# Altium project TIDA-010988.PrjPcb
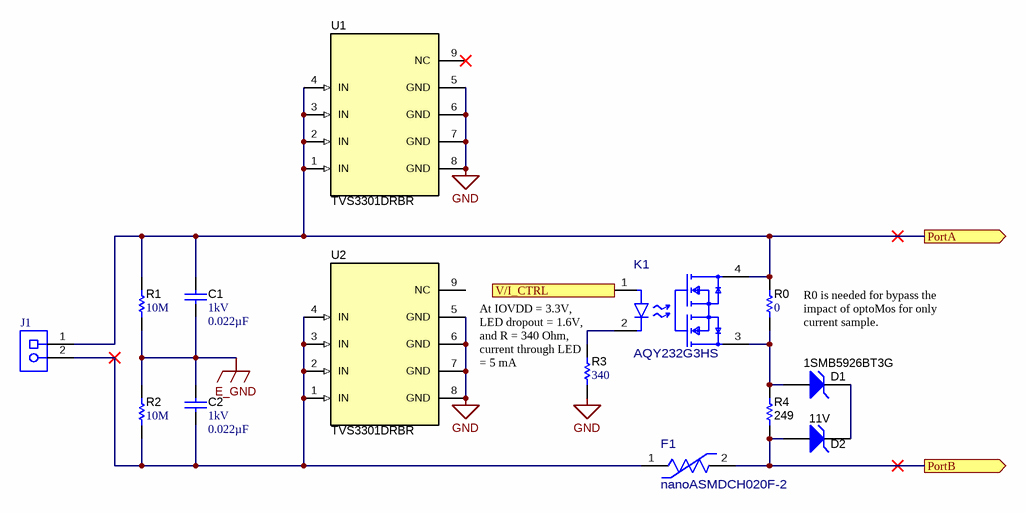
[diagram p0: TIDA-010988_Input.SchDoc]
CopyrightYear: 2025; PCB_Layout: Donna Xu; PCB_Rev: E1; PRJ_Customer: Public Release; PRJ_Engineer: Donna Xu; PRJ_Number: TIDA-010988; PRJ_Title: 8 CH V and I AIN module; SCH_Rev: E1; TechSupport: http://www.ti.com/support; TID: N/A
4 sheets, 173 parts. Net scope: flat (ports and power ports of the same name join across sheets).
Board file: TIDA-010988.PcbDoc
Sheets:
  TIDA-010988_Input.SchDoc
  TIDA-010988_ADC+MCU.SchDoc
  TIDA-010988_Power.SchDoc
  TIDA-010988_Hardware.SchDoc

## Sheet TIDA-010988_Input.SchDoc: INPUT
size A4; Date: Not shown in title block; ApprovedBy: Not shown in title block; CheckedBy: Not shown in title block; Author: Not shown in title block; CompanyName: Not shown in title block; DrawnBy: Donna Xu; Engineer: Not shown in title block; Organization: Not shown in title block; Address1: Not shown in title block; Address2: Not shown in title block; Address3: Not shown in title block; Address4: Not shown in title block; DocumentNumber: 1; Revision: Use project parameter SCH_Rev; SheetNumber: 2; SheetTotal: 5; PageSetup: Record=PageOptions¦CenterHorizontal=True¦CenterVertical=True¦PrintScale=0.93¦XCorrection=1.00¦YCorrection=1.00¦PrintKind=0¦BorderSize=5000000¦LeftOffset=0¦BottomOffset=0¦Orientation=2¦PaperLength=1000¦PaperWidth=1000¦Scale=100¦PaperSource=15¦PrintQuality=600¦MediaType=1¦DitherType=10¦PaperKind=Letter¦PrintScaleMode=1

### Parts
C1  VDC_V: 1kV  ValueDisplayed: 0.022µF  [1206_190]  (hidden comment: C1206C223KDRACTU)
C2  VDC_V: 1kV  ValueDisplayed: 0.022µF  [1206_190]  (hidden comment: C1206C223KDRACTU)
D1  1SMB5926BT3G  value 11V  [SMB]
D2  1SMB5926BT3G  [SMB]  (value not drawn)
F1  nanoASMDCH020F-2  [FP-nanoASMDCH020F-2_1206-MFG]
J1  691210910002  [Wurth_691210910002]  (value not drawn)
K1  AQY232G3HS  [FP-AQY232G3HS_SOP4-MFG]
R0  ValueDisplayed: 0  [0603]  (hidden comment: CRCW06030000Z0EA)
R1  ValueDisplayed: 10M  [0603]  (hidden comment: CRCW060310M0DHEAP)
R2  ValueDisplayed: 10M  [0603]  (hidden comment: CRCW060310M0DHEAP)
R3  ValueDisplayed: 340  [0603]  (hidden comment: RT0603BRD07340RL)
R4  ValueDisplayed: 249  [1206]  (hidden comment: TNPW1206249RBEEA)
U1  TVS3301DRBR  [DRB0008A]
U2  TVS3301DRBR  [DRB0008A]

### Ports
PortA (out), PortB (out), V/I_CTRL (in)

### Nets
E_GND: C1.2 C2.1 R1.1 R2.2
GND: R3.1 U1.5(GND) U1.6(GND) U1.7(GND) U1.8(GND) U2.5(GND) U2.6(GND) U2.7(GND) U2.8(GND)
PortA: C1.1 J1.1 K1.4(2_DRAIN) R0.2 R1.2 U1.1(IN) U1.2(IN) U1.3(IN) U1.4(IN) ; port PortA
PortB: D2.2(A) F1.2 R4.1 ; port PortB
V/I_CTRL: K1.1(ANODE) ; port V/I_CTRL
NetC2_2: C2.2 F1.1 J1.2 R2.1 U2.1(IN) U2.2(IN) U2.3(IN) U2.4(IN)
NetD1_1: D1.1(K) D2.1(K)
NetD1_2: D1.2(A) K1.3(1_DRAIN) R0.1 R4.2
NetK1_2: K1.2(CATHODE) R3.2

Not connected (* = marked no-connect by the designer): U1 9(NC)*; U2 9(NC)

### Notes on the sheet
- R0 is needed for bypass the impact of optoMos for only current sample.
- (near R3) At IOVDD = 3.3V,
  LED dropout = 1.6V,
  and R = 340 Ohm, current through LED = 5 mA

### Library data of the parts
C1 C2 = CMP-0084048-1: CAP, CERM, 0.022 µF, 1000 V,+/- 10%, X7R, AEC-Q200 Grade 1, 1206; Manufacturer: Kemet; TaMin_C: -55°C; Polarized: N; SizeAreaWB_mm2: 10.92; U/M: EA; Value: 0.022uF; TaMax_C: 125°C; SizeZ_mm: 1.9; SizeX_mm: 3.2; SizeY_mm: 1.6; Cap_Case: 1206; Value2: 1000V; SizeArea_mm2: 5.12; AEC Qualified: Y; Cap_F: 22nF; AEC Grade: 1; AEC Category: Q200
D1 = CMP-0005627-4: Diode, Zener, 11 V, 550 mW, SMB; Manufacturer: ON Semiconductor; AEC Category: Q101; SizeArea_mm2: 21.336; Power_W: 550mW; SizeY_mm: 3.81; SizeZ_mm: 2.6; Value1: 0.55W; SizeAreaWB_mm2: 44.156; RJA_CperW: 226; SizeX_mm: 5.6
D2 = CMP-0005627-4: Diode, Zener, 11 V, 550 mW, SMB; Manufacturer: ON Semiconductor; Value: 11V; AEC Category: Q101; SizeArea_mm2: 21.336; Power_W: 550mW; SizeY_mm: 3.81; SizeZ_mm: 2.6; Value1: 0.55W; SizeAreaWB_mm2: 44.156; RJA_CperW: 226; SizeX_mm: 5.6
F1 = CMP-0125283-2: Polymeric PTC Resettable Fuse 30V 200 mA Ih Surface Mount 1206 (3216 Metric), Concave; Manufacturer: Littelfuse; SizeZ_mm: 0.85mm; AEC Grade: Grade 1; AEC Qualified: Yes; Hold Current: 0.2A; Res_ohm: 0.6-4.5Ω; Trip Current: 0.6A; Trip Time: 0.01s
J1 = CMP-0054769-2: Receptacle, 2.54mm, 2x1, Tin, R/A, TH; Manufacturer: Wurth Elektronik; Row_Count: 1; Cert_UL: Y; CT: FALSE; Gender: Female; Pitch_mm: 2.54; Voltage_V: 150V; Current_A: 6A
K1 = CMP-0125248-1: Relay SSR 1mA 1.75V DC-IN 2A 60V AC/DC-OUT 4-Pin SOP Tube; Manufacturer: Panasonic; Contact Form: SPST-NO; SizeZ_mm: 2.4mm; AEC Qualified: No; Cap_F: 0.8pF; Input Current: 20mA; Max Power Dissipation: 530mW; On State Resistance: 0.07Ω; Output Voltage: 48V; Standoff Height: 0.1mm; TaMax_C: +125°C; TaMin_C: -40°C; TJmax_C: +130°C; Voltage_Isolation_Vrms: 3750Vrms
R0 = CMP-0025697-4: RES, 0, 5%, 0.1 W, AEC-Q200 Grade 0, 0603; Manufacturer: Vishay-Dale; Power_W: 100mW; TempCo: 200 ppm/C; Value_Code: 0000; Value: 0; EIA_Code: E24; SizeX_mm: 1.6; SizeY_mm: 0.8; SizeZ_mm: 1; Value2: 0.1W; SizeArea_mm2: 1.28; AEC Qualified: Y; VDC_V: 75V; AEC Category: Q200
R1 R2 = CMP-0023358-4: RES, 10 M, 0.5%, 0.1 W, AEC-Q200 Grade 0, 0603; Manufacturer: Vishay-Dale; Power_W: 100mW; TempCo: 50 ppm/C; Value_Code: 10M0; Value: 10Meg; EIA_Code: E24; SizeX_mm: 1.6; SizeY_mm: 0.8; SizeZ_mm: 1; Value2: 0.1W; SizeArea_mm2: 1.28; AEC Qualified: Y; VDC_V: 75V; AEC Grade: 0; AEC Category: Q200
R3 = CMP-0024131-2: RES, 340, 0.1%, 0.1 W, 0603; Manufacturer: Yageo America; Power_W: 100mW; TempCo: 25 ppm/C; Value_Code: 340R; U/M: EA; Value: 340; EIA_Code: E192; SizeX_mm: 1.6; SizeY_mm: 0.8; SizeZ_mm: 1; Value2: 0.1W; SizeArea_mm2: 1.28; VDC_V: 75V; AEC Category: Q200
R4 = CMP-0018822-2: RES, 249, 0.1%, 0.25 W, 1206; Manufacturer: Vishay-Dale; Power_W: 250mW; TempCo: 25 ppm/C; Value_Code: 249R; U/M: EA; Value: 249; EIA_Code: E192; SizeX_mm: 3.2; SizeY_mm: 1.6; SizeZ_mm: 1.35; Value2: 0.25W; SizeArea_mm2: 5.12; VDC_V: 200V; AEC Category: Q200
U1 U2 = CMP-0081715-3: 33 V Bidirectional Flat-Clamp Surge Protection Device, DRB0008A (VSON-8); Alternate PartNumber: TVS3301DRBT; Alternate Manufacturer: Texas Instruments; SizeZ_mm: 1.0; SizeX_mm: 3.0; AEC Category: Q200; SizeAreaWB_mm2: 16.0; CompType: IC; Rating: Catalog; SizeArea_mm2: 9.0; AEC Qualified: N

## Sheet TIDA-010988_ADC+MCU.SchDoc
size 431 x 279 mm; Date: Not shown in title block; ApprovedBy: Not shown in title block; CheckedBy: Not shown in title block; Author: Not shown in title block; CompanyName: Not shown in title block; DrawnBy: Donna Xu; Engineer: Not shown in title block; Organization: Not shown in title block; Address1: Not shown in title block; Address2: Not shown in title block; Address3: Not shown in title block; Address4: Not shown in title block; DocumentNumber: 2; Revision: Use project parameter SCH_Rev; SheetNumber: 3; SheetTotal: 5; PageSetup: Record=PageOptions¦CenterHorizontal=True¦CenterVertical=True¦PrintScale=1.00¦XCorrection=1.00¦YCorrection=1.00¦PrintKind=0¦BorderSize=5000000¦LeftOffset=0¦BottomOffset=0¦Orientation=2¦PaperLength=1000¦PaperWidth=1000¦Scale=100¦PaperSource=15¦PrintQuality=600¦MediaType=1¦DitherType=10¦PaperKind=Letter¦PrintScaleMode=1
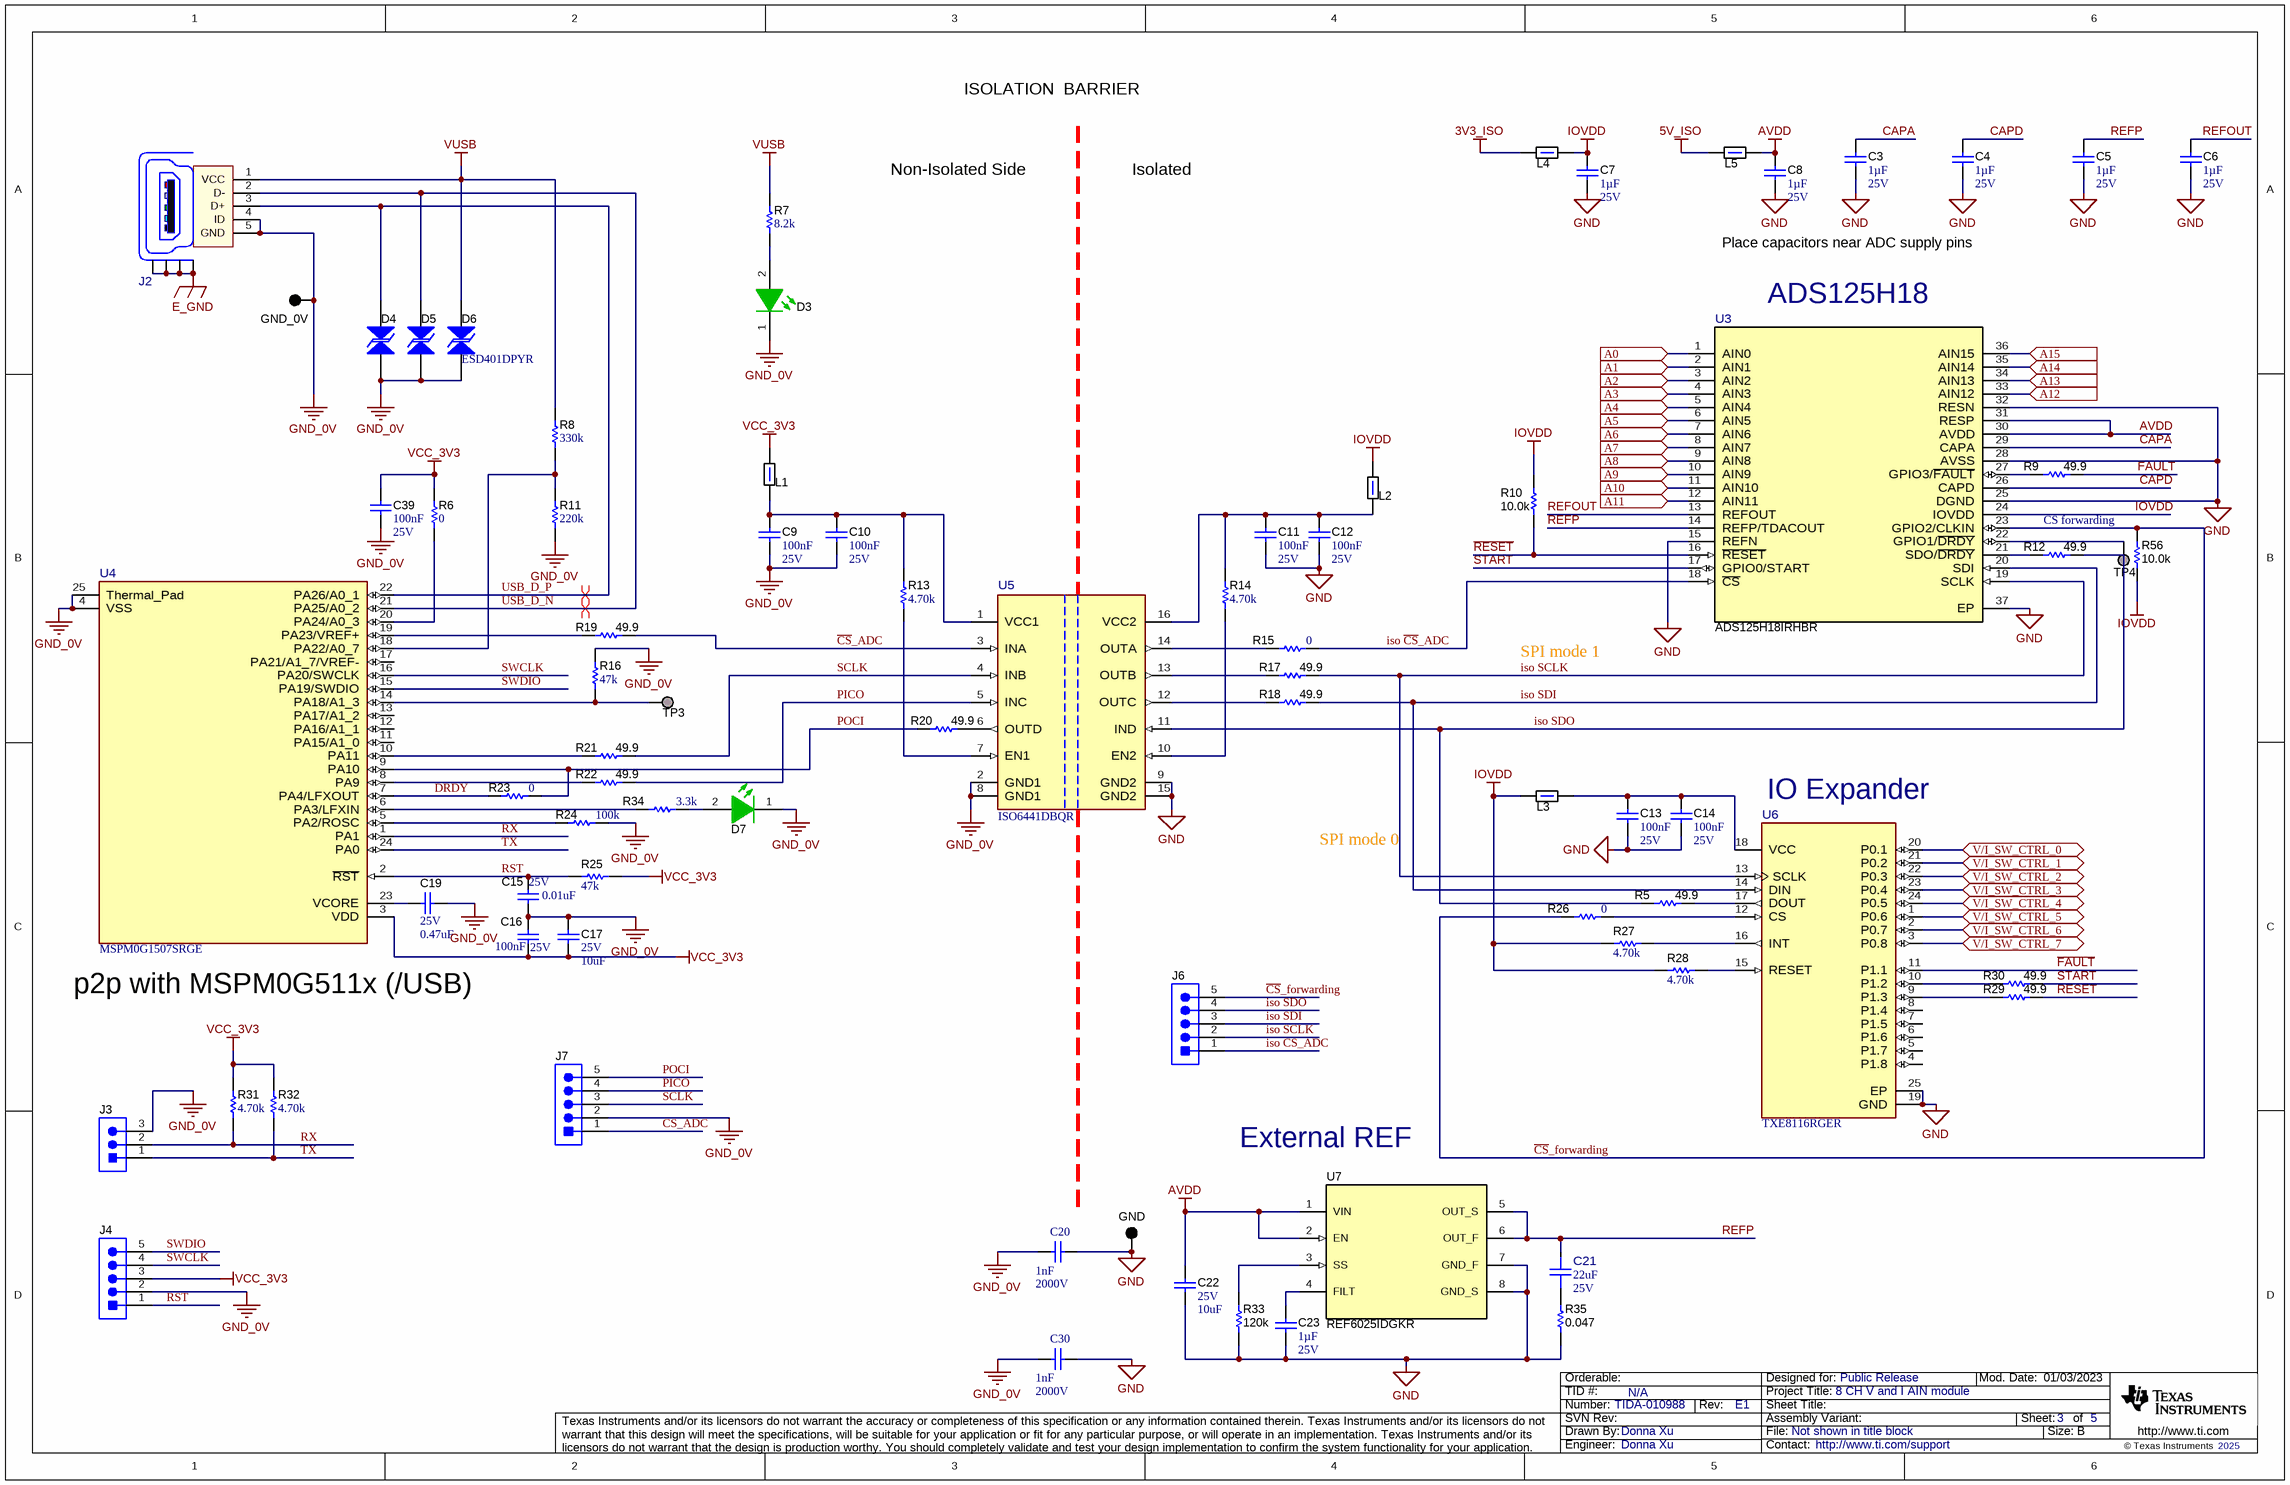
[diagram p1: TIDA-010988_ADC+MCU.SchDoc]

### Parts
C3  Cap_F: 1µF  VDC_V: 25V  [0603]  (hidden comment: 885012206076)
C4  Cap_F: 1µF  VDC_V: 25V  [0603]  (hidden comment: 885012206076)
C5  Cap_F: 1µF  VDC_V: 25V  [0603]  (hidden comment: 885012206076)
C6  Cap_F: 1µF  VDC_V: 25V  [0603S]  (hidden comment: 885012206076)
C7  Cap_F: 1µF  VDC_V: 25V  [0603S]  (hidden comment: 885012206076)
C8  Cap_F: 1µF  VDC_V: 25V  [0603]  (hidden comment: 885012206076)
C9  Cap_F: 100nF  VDC_V: 25V  [0603]  (hidden comment: 885012206071)
C10  Cap_F: 100nF  VDC_V: 25V  [0603]  (hidden comment: 885012206071)
C11  Cap_F: 100nF  VDC_V: 25V  [0603]  (hidden comment: 885012206071)
C12  Cap_F: 100nF  VDC_V: 25V  [0603]  (hidden comment: 885012206071)
C13  Cap_F: 100nF  VDC_V: 25V  [0603]  (hidden comment: 885012206071)
C14  Cap_F: 100nF  VDC_V: 25V  [0603]  (hidden comment: 885012206071)
C15  VDC_V: 25V  ValueDisplayed: 0.01uF  [0603]  (hidden comment: C0603H103J3GACTU)
C16  Cap_F: 100nF  VDC_V: 25V  [0603]  (hidden comment: 885012206071)
C17  VDC_V: 25V  ValueDisplayed: 10uF  [1206]  (hidden comment: 885012208069)
C19  VDC_V: 25V  ValueDisplayed: 0.47uF  [0805_HV]  (hidden comment: 08053D474KAT2A)
C20  Cap_F: 1nF  Rated Voltage (DC): 2000V  [WCAP-CSMH_1206_L3.2W1.6H1.6]  (hidden comment: 885342208024)
C21  ValueDisplayed: 22uF  VDC_V: 25V  [FP-885012209074_1210-MFG]  (hidden comment: 885012209074)
C22  VDC_V: 25V  ValueDisplayed: 10uF  [1206]  (hidden comment: 885012208069)
C23  Cap_F: 1µF  VDC_V: 25V  [0603]  (hidden comment: 885012206076)
C30  Cap_F: 1nF  Rated Voltage (DC): 2000V  [WCAP-CSMH_1206_L3.2W1.6H1.6]  (hidden comment: 885342208024)
C39  Cap_F: 100nF  VDC_V: 25V  [0603]  (hidden comment: 885012206071)
D3  150040GS73240  [WL-SMCC_0402_Green]  (value not drawn)
D4  ESD401DPYR  [DPY0002A]  (value not drawn)
D5  ESD401DPYR  [DPY0002A]  (value not drawn)
D6  ESD401DPYR  [DPY0002A]
D7  150040GS73240  [WL-SMCC_0402_Green]  (value not drawn)
J2  629105150521  [FP-629105150521_CONN_USB_8MM0_6MM6-MFG]  (value not drawn)
J3  61300311121  [WURTH_61300311121]  (value not drawn)
J4  M22-2510505  [Harwin_M22-2510505]  (value not drawn)
J6  M22-2510505  [Harwin_M22-2510505]  (value not drawn)
J7  M22-2510505  [Harwin_M22-2510505]  (value not drawn)
L1  782633601  [0603]  (value not drawn)
L2  782633601  [0603]  (value not drawn)
L3  782633601  [0603]  (value not drawn)
L4  782633601  [0603]  (value not drawn)
L5  782633601  [0603]  (value not drawn)
R5  ValueDisplayed: 49.9  [0603]  (hidden comment: RT0603DRE0749R9L)
R6  ValueDisplayed: 0  [0603]  (hidden comment: CRCW06030000Z0EA)
R7  ValueDisplayed: 8.2k  [0603]  (hidden comment: CRCW06038K20JNEA)
R8  ValueDisplayed: 330k  [0603]  (hidden comment: RC0603FR-07330KL)
R9  ValueDisplayed: 49.9  [0603]  (hidden comment: RT0603DRE0749R9L)
R10  ValueDisplayed: 10.0k  [0603S]  (hidden comment: CRCW060310K0FKEA)
R11  ValueDisplayed: 220k  [0603]  (hidden comment: RC0603FR-07220KL)
R12  ValueDisplayed: 49.9  [0603S]  (hidden comment: RT0603DRE0749R9L)
R13  ValueDisplayed: 4.70k  [0603S]  (hidden comment: RC0603FR-074K7L)
R14  ValueDisplayed: 4.70k  [0603S]  (hidden comment: RC0603FR-074K7L)
R15  ValueDisplayed: 0  [0603S]  (hidden comment: CRCW06030000Z0EA)
R16  ValueDisplayed: 47k  [0603]  (hidden comment: RC0603JR-0747KL)
R17  ValueDisplayed: 49.9  [0603S]  (hidden comment: RT0603DRE0749R9L)
R18  ValueDisplayed: 49.9  [0603S]  (hidden comment: RT0603DRE0749R9L)
R19  ValueDisplayed: 49.9  [0603]  (hidden comment: RT0603DRE0749R9L)
R20  ValueDisplayed: 49.9  [0603S]  (hidden comment: RT0603DRE0749R9L)
R21  ValueDisplayed: 49.9  [0603S]  (hidden comment: RT0603DRE0749R9L)
R22  ValueDisplayed: 49.9  [0603S]  (hidden comment: RT0603DRE0749R9L)
R23  ValueDisplayed: 0  [0603S]  (hidden comment: CRCW06030000Z0EA)
R24  ValueDisplayed: 100k  [0603]  (hidden comment: ERA-3AEB104V)
R25  ValueDisplayed: 47k  [0603]  (hidden comment: RC0603JR-0747KL)
R26  ValueDisplayed: 0  [0603]  (hidden comment: CRCW06030000Z0EA)
R27  ValueDisplayed: 4.70k  [0603]  (hidden comment: RC0603FR-074K7L)
R28  ValueDisplayed: 4.70k  [0603]  (hidden comment: RC0603FR-074K7L)
R29  ValueDisplayed: 49.9  [0603]  (hidden comment: RT0603DRE0749R9L)
R30  ValueDisplayed: 49.9  [0603]  (hidden comment: RT0603DRE0749R9L)
R31  ValueDisplayed: 4.70k  [0603]  (hidden comment: RC0603FR-074K7L)
R32  ValueDisplayed: 4.70k  [0603]  (hidden comment: RC0603FR-074K7L)
R33  ValueDisplayed: 120k  [0603]  (hidden comment: RG1608P-124-B-T5)
R34  ValueDisplayed: 3.3k  [0402]  (hidden comment: CRCW04023K30JNED)
R35  ValueDisplayed: 0.047  [0603]  (hidden comment: ERJ-L03KF47MV)
R56  ValueDisplayed: 10.0k  [0603S]  (hidden comment: CRCW060310K0FKEA)
TP1  GND  [Keystone5001]
TP2  GND_0V  [Keystone5001]
TP3  PA18  [TP_SM_1MM]  (value not drawn)  (no BOM)
TP4  DRDY  [TP_SM_1MM]  (value not drawn)  (no BOM)
U3  ADS125H18IRHBR  [RHB0036A-MFG]
U4  MSPM0G1507SRGE  [RGE0024H-MFG]
U5  ISO6441DBQR  [DBQ0016A-MFG]
U6  TXE8116RGER  [RGE0024F-MFG]
U7  REF6025IDGKR  [DGK0008A_N]

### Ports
A0 (in), A1 (in), A2 (in), A3 (in), A4 (in), A5 (in), A6 (in), A7 (in), A8 (in), A9 (in), A10 (in), A11 (in), A12 (in), A13 (in), A14 (in), A15 (in), V/I_SW_CTRL_0 (bidir), V/I_SW_CTRL_1 (bidir), V/I_SW_CTRL_2 (bidir), V/I_SW_CTRL_3 (bidir), V/I_SW_CTRL_4 (bidir), V/I_SW_CTRL_5 (bidir), V/I_SW_CTRL_6 (bidir), V/I_SW_CTRL_7 (bidir)

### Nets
3V3_ISO: L4.2
5V_ISO: L5.2
AVDD: C8.1 C22.1 L5.1 U3.30(AVDD) U3.31(RESP) U7.1(VIN) U7.2(EN)
E_GND: J2.Z1(Shield) J2.Z2(Shield) J2.Z3(Shield) J2.Z4(Shield)
GND: C3.2 C4.2 C5.2 C6.2 C7.2 C8.2 C11.2 C12.2 C13.2 C14.2 C20.2 C22.2 C23.2 C30.2 R33.1 R35.1 TP1.1 U3.15(REFN) U3.25(DGND) U3.28(AVSS) U3.32(RESN) U3.37(EP) U5.9(GND2) U5.15(GND2) U6.19(GND) U6.25(EP) U7.7(GND_F) U7.8(GND_S)
GND_0V: C9.2 C10.2 C15.2 C16.1 C17.1 C19.1 C20.1 C30.1 C39.2 D3.1(K) D4.1 D5.1 D6.1 D7.1(K) J2.4(ID) J2.5(GND) J3.3 J4.2 J7.2 R11.1 R16.1 R24.2 TP2.1 U4.4(VSS) U4.25(Thermal_Pad) U5.2(GND1) U5.8(GND1)
IOVDD: C7.1 L2.2 L3.1 L4.1 R10.1 R27.2 R28.2 R56.1 U3.24(IOVDD)
VCC_3V3: C16.2 C17.2 C39.1 J4.3 L1.1 R6.2 R25.1 R31.2 R32.2 U4.3(VDD)
VUSB: D6.2 J2.1(VCC) R7.2 R8.2
A0: U3.1(AIN0) ; port A0
A1: U3.2(AIN1) ; port A1
A2: U3.3(AIN2) ; port A2
A3: U3.4(AIN3) ; port A3
A4: U3.5(AIN4) ; port A4
A5: U3.6(AIN5) ; port A5
A6: U3.7(AIN6) ; port A6
A7: U3.8(AIN7) ; port A7
A8: U3.9(AIN8) ; port A8
A9: U3.10(AIN9) ; port A9
A10: U3.11(AIN10) ; port A10
A11: U3.12(AIN11) ; port A11
A12: U3.33(AIN12) ; port A12
A13: U3.34(AIN13) ; port A13
A14: U3.35(AIN14) ; port A14
A15: U3.36(AIN15) ; port A15
~{CS}_ADC: J7.1 R19.2 U5.3(INA)
~{CS}_forwarding: J6.5 R26.1 R56.2 U3.23(GPIO2/CLKIN)
CAPA: C3.1 U3.29(CAPA)
CAPD: C4.1 U3.26(CAPD)
DRDY: R23.1 U4.7(PA4/LFXOUT)
~{FAULT}: R9.2 U6.11(P1.1)
iso ~{CS}_ADC: J6.1 R15.2 U3.18(~{CS})
iso SCLK: J6.2 R17.2 U3.19(SCLK) U6.13(SCLK)
iso SDI: J6.3 R18.2 U3.20(SDI) U6.14(DIN)
iso SDO: J6.4 R5.1 R12.2 U5.11(IND)
PICO: J7.4 R22.2 U5.5(INC)
POCI: J7.5 R20.1 R23.2 U4.9(PA10)
~{RESET}: R10.2 R29.2 U3.16(~{RESET})
REFOUT: C6.1 U3.13(REFOUT)
REFP: C5.1 C21.2 U3.14(REFP/TDACOUT) U7.5(OUT_S) U7.6(OUT_F)
RST: C15.1 J4.1 R25.2 U4.2(~{RST})
RX: J3.2 R31.1 U4.1(PA1)
SCLK: J7.3 R21.2 U5.4(INB)
START: R30.2 U3.17(GPIO0/START)
SWCLK: J4.4 U4.16(PA20/SWCLK)
SWDIO: J4.5 U4.15(PA19/SWDIO)
TX: J3.1 R32.1 U4.24(PA0)
USB_D_N: D5.2 J2.2(D-) U4.21(PA25/A0_2)
USB_D_P: D4.2 J2.3(D+) U4.22(PA26/A0_1)
V/I_SW_CTRL_0: U6.20(P0.1) ; port V/I_SW_CTRL_0
V/I_SW_CTRL_1: U6.21(P0.2) ; port V/I_SW_CTRL_1
V/I_SW_CTRL_2: U6.22(P0.3) ; port V/I_SW_CTRL_2
V/I_SW_CTRL_3: U6.23(P0.4) ; port V/I_SW_CTRL_3
V/I_SW_CTRL_4: U6.24(P0.5) ; port V/I_SW_CTRL_4
V/I_SW_CTRL_5: U6.1(P0.6) ; port V/I_SW_CTRL_5
V/I_SW_CTRL_6: U6.2(P0.7) ; port V/I_SW_CTRL_6
V/I_SW_CTRL_7: U6.3(P0.8) ; port V/I_SW_CTRL_7
NetC9_1: C9.1 C10.1 L1.2 R13.2 U5.1(VCC1)
NetC11_1: C11.1 C12.1 L2.1 R14.2 U5.16(VCC2)
NetC13_1: C13.1 C14.1 L3.2 U6.18(VCC)
NetC19_2: C19.2 U4.23(VCORE)
NetC21_1: C21.1 R35.2
NetC23_1: C23.1 U7.4(FILT)
NetD3_2: D3.2(A) R7.1
NetD7_2: D7.2(A) R34.2
NetR5_2: R5.2 U6.17(DOUT)
NetR6_1: R6.1 U4.20(PA24/A0_3)
NetR8_1: R8.1 R11.2 U4.18(PA22/A0_7)
NetR9_1: R9.1 U3.27(GPIO3/~{FAULT})
NetR12_1: R12.1 U3.21(SDO/~{DRDY})
NetR13_1: R13.1 U5.7(EN1)
NetR14_1: R14.1 U5.10(EN2)
NetR15_1: R15.1 U5.14(OUTA)
NetR16_2: R16.2 TP3.1 U4.14(PA18/A1_3)
NetR17_1: R17.1 U5.13(OUTB)
NetR18_1: R18.1 U5.12(OUTC)
NetR19_1: R19.1 U4.19(PA23/VREF+)
NetR20_2: R20.2 U5.6(OUTD)
NetR21_1: R21.1 U4.10(PA11)
NetR22_1: R22.1 U4.8(PA9)
NetR24_1: R24.1 U4.5(PA2/ROSC)
NetR26_2: R26.2 U6.12(CS)
NetR27_1: R27.1 U6.16(INT)
NetR28_1: R28.1 U6.15(RESET)
NetR29_1: R29.1 U6.9(P1.3)
NetR30_1: R30.1 U6.10(P1.2)
NetR33_2: R33.2 U7.3(SS)
NetR34_1: R34.1 U4.6(PA3/LFXIN)
NetTP4_1: TP4.1 U3.22(GPIO1/~{DRDY})

Not connected (* = marked no-connect by the designer): U4 11(PA15/A1_0) 12(PA16/A1_1) 13(PA17/A1_2) 17(PA21/A1_7/VREF-); U6 4(P1.8) 5(P1.7) 6(P1.6) 7(P1.5) 8(P1.4)

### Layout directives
differential pair; differential pair class D90: USB_D_P
differential pair: USB_D_N

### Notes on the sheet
- ISOLATION  BARRIER
- Non-Isolated Side
- Isolated Side
- Place capacitors near ADC supply pins
- (near U3) ADS125H18
- CS forwarding
- SPI mode 1
- (near U6) IO Expander
- SPI mode 0
- p2p with MSPM0G511x (/USB)
- External REF

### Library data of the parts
C3-C5 C8 C23 = CMP-0006833-4: CAP, CERM, 1 uF, 25 V, +/- 10%, X7R, 0603; Manufacturer: Wurth Elektronik; TaMin_C: -55°C; Polarized: N; SizeAreaWB_mm2: 4.68; Value1: Unknown; U/M: EA; Value: 1uF; TaMax_C: 125°C; SizeZ_mm: 1; SizeX_mm: 1.6; SizeY_mm: 0.8; SizeArea_mm2: 1.28; AEC Category: Q200
C6 C7 = CMP-0006833-4: CAP, CERM, 1 uF, 25 V, +/- 10%, X7R, 0603; Manufacturer: Wurth Elektronik; TaMin_C: -55°C; Polarized: N; SizeAreaWB_mm2: 4.68; Value1: Unknown; U/M: EA; Value: 1uF; TaMax_C: 125°C; SizeZ_mm: 1; SizeX_mm: 1.6; SizeY_mm: 0.8; Cap_Case: 0603; SizeArea_mm2: 1.28; AEC Category: Q200
C9-C14 C16 C39 = CMP-0006832-5: CAP, CERM, 0.1 uF, 25 V, +/- 10%, X7R, 0603; Manufacturer: Wurth Elektronik; TaMin_C: -55°C; Polarized: N; SizeAreaWB_mm2: 4.68; Value1: Unknown; U/M: EA; Value: 0.1uF; TaMax_C: 125°C; SizeZ_mm: 1; SizeX_mm: 1.6; SizeY_mm: 0.8; SizeArea_mm2: 1.28; AEC Category: Q200
C15 = CMP-0006975-4: CAP, CERM, 0.01 uF, 25 V, +/- 5%, C0G/NP0, 0603; Manufacturer: Kemet; TaMin_C: -55°C; Polarized: N; SizeAreaWB_mm2: 4.68; Value1: Unknown; U/M: EA; Value: 0.01uF; TaMax_C: 200°C; SizeZ_mm: 1; SizeX_mm: 1.6; SizeY_mm: 0.8; SizeArea_mm2: 1.28; Cap_F: 10nF; AEC Category: Q200
C17 C22 = CMP-0008574-2: CAP, CERM, 10 uF, 25 V, +/- 10%, X7R, 1206; Manufacturer: Wurth Elektronik; TaMin_C: -55°C; Polarized: N; SizeAreaWB_mm2: 10.92; Value1: Unknown; U/M: EA; Value: 10uF; TaMax_C: 125°C; SizeZ_mm: 1.35; SizeX_mm: 3.2; SizeY_mm: 1.6; SizeArea_mm2: 5.12; Cap_F: 10µF; AEC Category: Q200
C19 = CMP-0007576-2: CAP, CERM, 0.47 uF, 25 V, +/- 10%, X5R, 0805; Manufacturer: AVX; TaMin_C: -55°C; ESR_ohm: 0.017; Polarized: N; SizeAreaWB_mm2: 6.75; Value1: 0.017 ohm; U/M: EA; Value: 0.47uF; TaMax_C: 85°C; SizeZ_mm: 1.45; SizeX_mm: 2; SizeY_mm: 1.25; Cap_Case: 0805; SizeArea_mm2: 2.5; Cap_F: 470nF; AEC Category: Q200
C20 C30 = CMP-0119825-1: WCAP-CSMH Multilayer Ceramic Chip Capacitor, Mid and High Voltage, size 1206, X7R Class II, 1nF, 2000VDC; Manufacturer: Wurth Elektronik; Capacitance Tolerance: 10%; Case/Size Code: 1206; Dissipation Factor: 2.5%; Insulation Resistance: 10GOhm; Technical Reference: X7R1206102KB00DFCT10000
C21 = CMP-0096740-1: 22 µF ±10% 25V Ceramic Capacitor X7R 1210 (3225 Metric); Manufacturer: Wurth; AEC Qualified: No; Cap_F: 22µF; SizeZ_mm: 2.7mm; Value: 22µF; TempCo: 15%
D3 D7 = CMP-0081765-2: LED, Green, SMD; Manufacturer: Wurth Elektronik; Vr_V: 5V; Io_A: 20mA; Tjmax_C: 95°C; Ir_A: 10µA; Power_TotalModule: 99mW; Value2: 3.2V; SizeArea_mm2: 0.5; SizeX_mm: 1; Value1: 0.099W; Angle: 120; Type: InGaN; SizeAreaWB_mm2: 3
D4-D6 = CMP-0074647-4: 1-Channel ESD Protection Diode with Low RDYN and Low Clamping Voltage, DPY0002A (X1SON-2); Manufacturer: Texas Instruments; Alternate PartNumber: ESD401DPYT; Rating: Catalog; SizeAreaWB_mm2: 3.2; AEC Category: Q200; SizeZ_mm: 0.45; SizeArea_mm2: 0.6; SizeX_mm: 1.0; CompType: IC
J2 = CMP-0086695-3: USB - micro B USB 2.0 Receptacle Connector 5 Position Surface Mount, Right Angle; Through Hole; Manufacturer: Wurth Electronics; Shrouded: true; Voltage_V: 30V; Current_A: 3A; ContactFinish: Gold
J3 = CMP-0054796-4: Header, 2.54 mm, 3x1, Gold, TH; Manufacturer: Wurth Elektronik; Green_REACh: Passed; CT: FALSE; CNHeader: TRUE; Green_Lifecycle: Active
J4 J6 J7 = CMP-0075212-1: Header, 2mm, 5x1, Gold, TH; Manufacturer: Harwin; CNHeader: True; Current_A: 1A; Shrouded: N; Gender: Male; Voltage_V: 500V; Row_Count: 1; Pitch_mm: 2; CT: False; Cert_UL: Y
L1-L5 = CMP-0003285-2: Ferrite Bead, 600 ohm @ 100 MHz, 1 A, 0603; Manufacturer: Wurth Elektronik; Ztyp@1GHz_Ohm: 228.849; ZTyp@100MHz_Ohm: 600; SizeAreaWB_mm2: 4.68; DCR_ohm: 0.2; Value1: 0.2 ohm; Value: 600 ohm; Imax_A: 1A; SizeZ_mm: 1; SizeX_mm: 1.6; SizeY_mm: 0.8; SizeArea_mm2: 1.28
R5 R9 R12 R17-R22 R29 R30 = CMP-0025334-3: RES, 49.9, 0.5%, 0.1 W, 0603; Manufacturer: Yageo America; Power_W: 100mW; TempCo: 50 ppm/C; Value_Code: 49R9; U/M: EA; Value: 49.9; EIA_Code: E192; SizeX_mm: 1.6; SizeY_mm: 0.8; SizeZ_mm: 1; Value2: 0.1W; SizeArea_mm2: 1.28; VDC_V: 75V; AEC Category: Q200
R6 R15 R23 R26 = CMP-0025697-4: as R0 on sheet TIDA-010988_Input
R7 = CMP-0025862-4: RES, 8.2 k, 5%, 0.1 W, AEC-Q200 Grade 0, 0603; Manufacturer: Vishay-Dale; Power_W: 100mW; TempCo: 200 ppm/C; Value_Code: 8k20; Value: 8.2k; EIA_Code: E24; SizeX_mm: 1.6; SizeY_mm: 0.8; SizeZ_mm: 1; Value2: 0.1W; SizeArea_mm2: 1.28; AEC Qualified: Y; VDC_V: 75V; AEC Category: Q200; AEC Grade: 0
R8 = CMP-0023032-4: RES, 330 k, 1%, 0.1 W, 0603; Manufacturer: Yageo; Power_W: 100mW; TempCo: 100 ppm/C; Value: 330k; SizeX_mm: 1.6; SizeY_mm: 0.8; SizeZ_mm: 1; Value2: 0.1W; SizeArea_mm2: 1.28; AEC Qualified: N; VDC_V: 75V; AEC Category: Q200; SizeAreaWB_mm2: 4.68
R10 R56 = CMP-0021998-4: RES, 10.0 k, 1%, 0.1 W, AEC-Q200 Grade 0, 0603; Manufacturer: Vishay-Dale; Power_W: 100mW; TempCo: 100 ppm/C; Value_Code: 10k0; Value: 10.0k; EIA_Code: E96; Res_ohm: 10k; SizeX_mm: 1.6; SizeY_mm: 0.8; SizeZ_mm: 1; Value2: 0.1W; SizeArea_mm2: 1.28; AEC Qualified: Y; VDC_V: 75V; AEC Category: Q200; AEC Grade: 0
R11 = CMP-0022917-4: RES, 220 k, 1%, 0.1 W, 0603; Manufacturer: Yageo; Power_W: 100mW; TempCo: 100 ppm/C; Value: 220k; SizeX_mm: 1.6; SizeY_mm: 0.8; SizeZ_mm: 1; Value2: 0.1W; SizeArea_mm2: 1.28; AEC Qualified: N; VDC_V: 75V; AEC Category: Q200; SizeAreaWB_mm2: 4.68
R13 R14 R27 R28 R31 R32 = CMP-0023153-5: RES, 4.70 k, 1%, 0.1 W, 0603; Manufacturer: Yageo; Power_W: 100mW; TempCo: 100 ppm/C; Value_Code: 4k70; Value: 4.70k; Res_ohm: 4.7k; SizeX_mm: 1.6; SizeY_mm: 0.8; SizeZ_mm: 1; Value2: 0.1W; SizeArea_mm2: 1.28; AEC Qualified: N; VDC_V: 75V; AEC Category: Q200; SizeAreaWB_mm2: 4.68
R16 R25 = CMP-0025925-5: RES, 47 k, 5%, 0.1 W, 0603; Manufacturer: Yageo; Power_W: 100mW; TempCo: 100 ppm/C; Value_Code: 47k0; Value: 47k; EIA_Code: E24; SizeX_mm: 1.6; SizeY_mm: 0.8; SizeZ_mm: 1; Value2: 0.1W; SizeArea_mm2: 1.28; AEC Qualified: N; VDC_V: 75V; AEC Category: Q200; SizeAreaWB_mm2: 4.68
R24 = CMP-0023363-3: RES, 100 k, 0.1%, 0.1 W, AEC-Q200 Grade 0, 0603; Manufacturer: Panasonic; Power_W: 100mW; TempCo: 25 ppm/C; U/M: EA; Value: 100k; EIA_Code: E192; SizeX_mm: 1.6; SizeY_mm: 0.8; SizeZ_mm: 1; Value2: 0.1W; SizeArea_mm2: 1.28; AEC Qualified: Y; VDC_V: 75V; AEC Grade: 0; AEC Category: Q200
R33 = CMP-0023427-3: RES, 120 k, 0.1%, 0.1 W, 0603; Manufacturer: Susumu Co Ltd; Power_W: 100mW; TempCo: 25 ppm/C; U/M: EA; Value: 120k; EIA_Code: E192; SizeX_mm: 1.6; SizeY_mm: 0.8; SizeZ_mm: 1; Value2: 0.1W; SizeArea_mm2: 1.28; VDC_V: 75V; AEC Category: Q200
R34 = CMP-0026918-5: RES, 3.3 k, 5%, 0.063 W, AEC-Q200 Grade 0, 0402; Manufacturer: Vishay-Dale; Power_W: 63mW; TempCo: 200 ppm/C; Value_Code: 3k30; Value: 3.3k; EIA_Code: E24; SizeX_mm: 1; SizeY_mm: 0.5; SizeZ_mm: 0.6; Value2: 0.063W; AEC Qualified: Y; VDC_V: 50V; AEC Category: Q200; AEC Grade: 0
R35 = CMP-0022726-3: RES, 0.047, 1%, 0.1 W, AEC-Q200 Grade 1, 0603; Manufacturer: Panasonic; Power_W: 100mW; TempCo: 200 ppm/C; Value_Code: R047; Value: 0.047; EIA_Code: E96; SizeX_mm: 1.6; SizeY_mm: 0.8; SizeZ_mm: 1; Value2: 0.1W; SizeArea_mm2: 1.28; AEC Qualified: Y; AEC Category: Q200; SizeAreaWB_mm2: 4.68
TP1 TP2 = CMP-0055138-2: Test Point, Miniature, Black, TH; Manufacturer: Keystone Electronics; CNHeader: FALSE; Green_Lifecycle: Active; Green_REACh: Passed; ContactFinish: Silver; CT: TRUE
TP3 TP4 = CMP-0003825-1: 1mm Test Point, SMT; Manufacturer: Any
U3 = CMP-0120762-1: Manufacturer: Texas Instruments; SizeZ_mm: 1mm; Standoff Height: 0mm
U4 = CMP-0093957-1: Mixed-Signal Microcontroller, VQFN24; Manufacturer: Texas Instruments; Number Of I2C Channels: 2; Number Of I/Os: 20; AEC Qualified: No; Frequency_Fixed: 80MHz; Standoff Height: 0mm; Number Of Pwm Channels: 6; Core Architecture: ARM Cortex-M0+; Interface: I2C,SPI,UART,LIN,IrDA,SMBus,Other; TaMax_C: +125°C; SizeZ_mm: 1mm; Memory Size: 128KBytes; TJmax_C: +130°C; Number Of Cores: 1; Min Supply Voltage: 1.62V; Memory Type: FLASH; Ram Size: 32KBytes; Number Of Uart Channels: 4; Max Supply Voltage: 3.6V; TaMin_C: -40°C; Data Bus Width: 32bits; Number Of Adc Channels: 9
U5 = CMP-0127533-1: General-Purpose, Basic and Reinforced, Quad-Channel Digital Isolators; Manufacturer: Texas Instruments; SizeZ_mm: 1.75mm; AEC Qualified: No; Max Supply Voltage: 5.5V; Min Supply Voltage: 2.25V; Standoff Height: 0.11mm; TaMax_C: +125°C; TaMin_C: -40°C; TJmax_C: +150°C
U6 = CMP-0122830-1: Manufacturer: Texas Instruments; SizeZ_mm: 1mm; Standoff Height: 0mm
U7 = CMP-0076433-2: 5ppm/C High-Precision Voltage Reference with Integrated High-Bandwidth Buffer, DGK0008A (VSSOP-8); Manufacturer: Texas Instruments; Alternate PartNumber: REF6025IDGKT; SizeAreaWB_mm2: 23.6; SizeArea_mm2: 14.7; SizeZ_mm: 1.1; SizeY_mm: 3; CompType: IC; SizeX_mm: 4.9; AEC Category: Q200; AEC Qualified: N

## Sheet TIDA-010988_Power.SchDoc
size 431 x 279 mm; Date: Not shown in title block; ApprovedBy: Not shown in title block; CheckedBy: Not shown in title block; Author: Not shown in title block; CompanyName: Not shown in title block; DrawnBy: Donna Xu; Engineer: Not shown in title block; Organization: Not shown in title block; Address1: Not shown in title block; Address2: Not shown in title block; Address3: Not shown in title block; Address4: Not shown in title block; DocumentNumber: 2; Revision: Use project parameter SCH_Rev; SheetNumber: 4; SheetTotal: 5; PageSetup: Record=PageOptions¦CenterHorizontal=True¦CenterVertical=True¦PrintScale=1.00¦XCorrection=1.00¦YCorrection=1.00¦PrintKind=0¦BorderSize=5000000¦LeftOffset=0¦BottomOffset=0¦Orientation=2¦PaperLength=1000¦PaperWidth=1000¦Scale=100¦PaperSource=15¦PrintQuality=600¦MediaType=1¦DitherType=10¦PaperKind=Letter¦PrintScaleMode=1
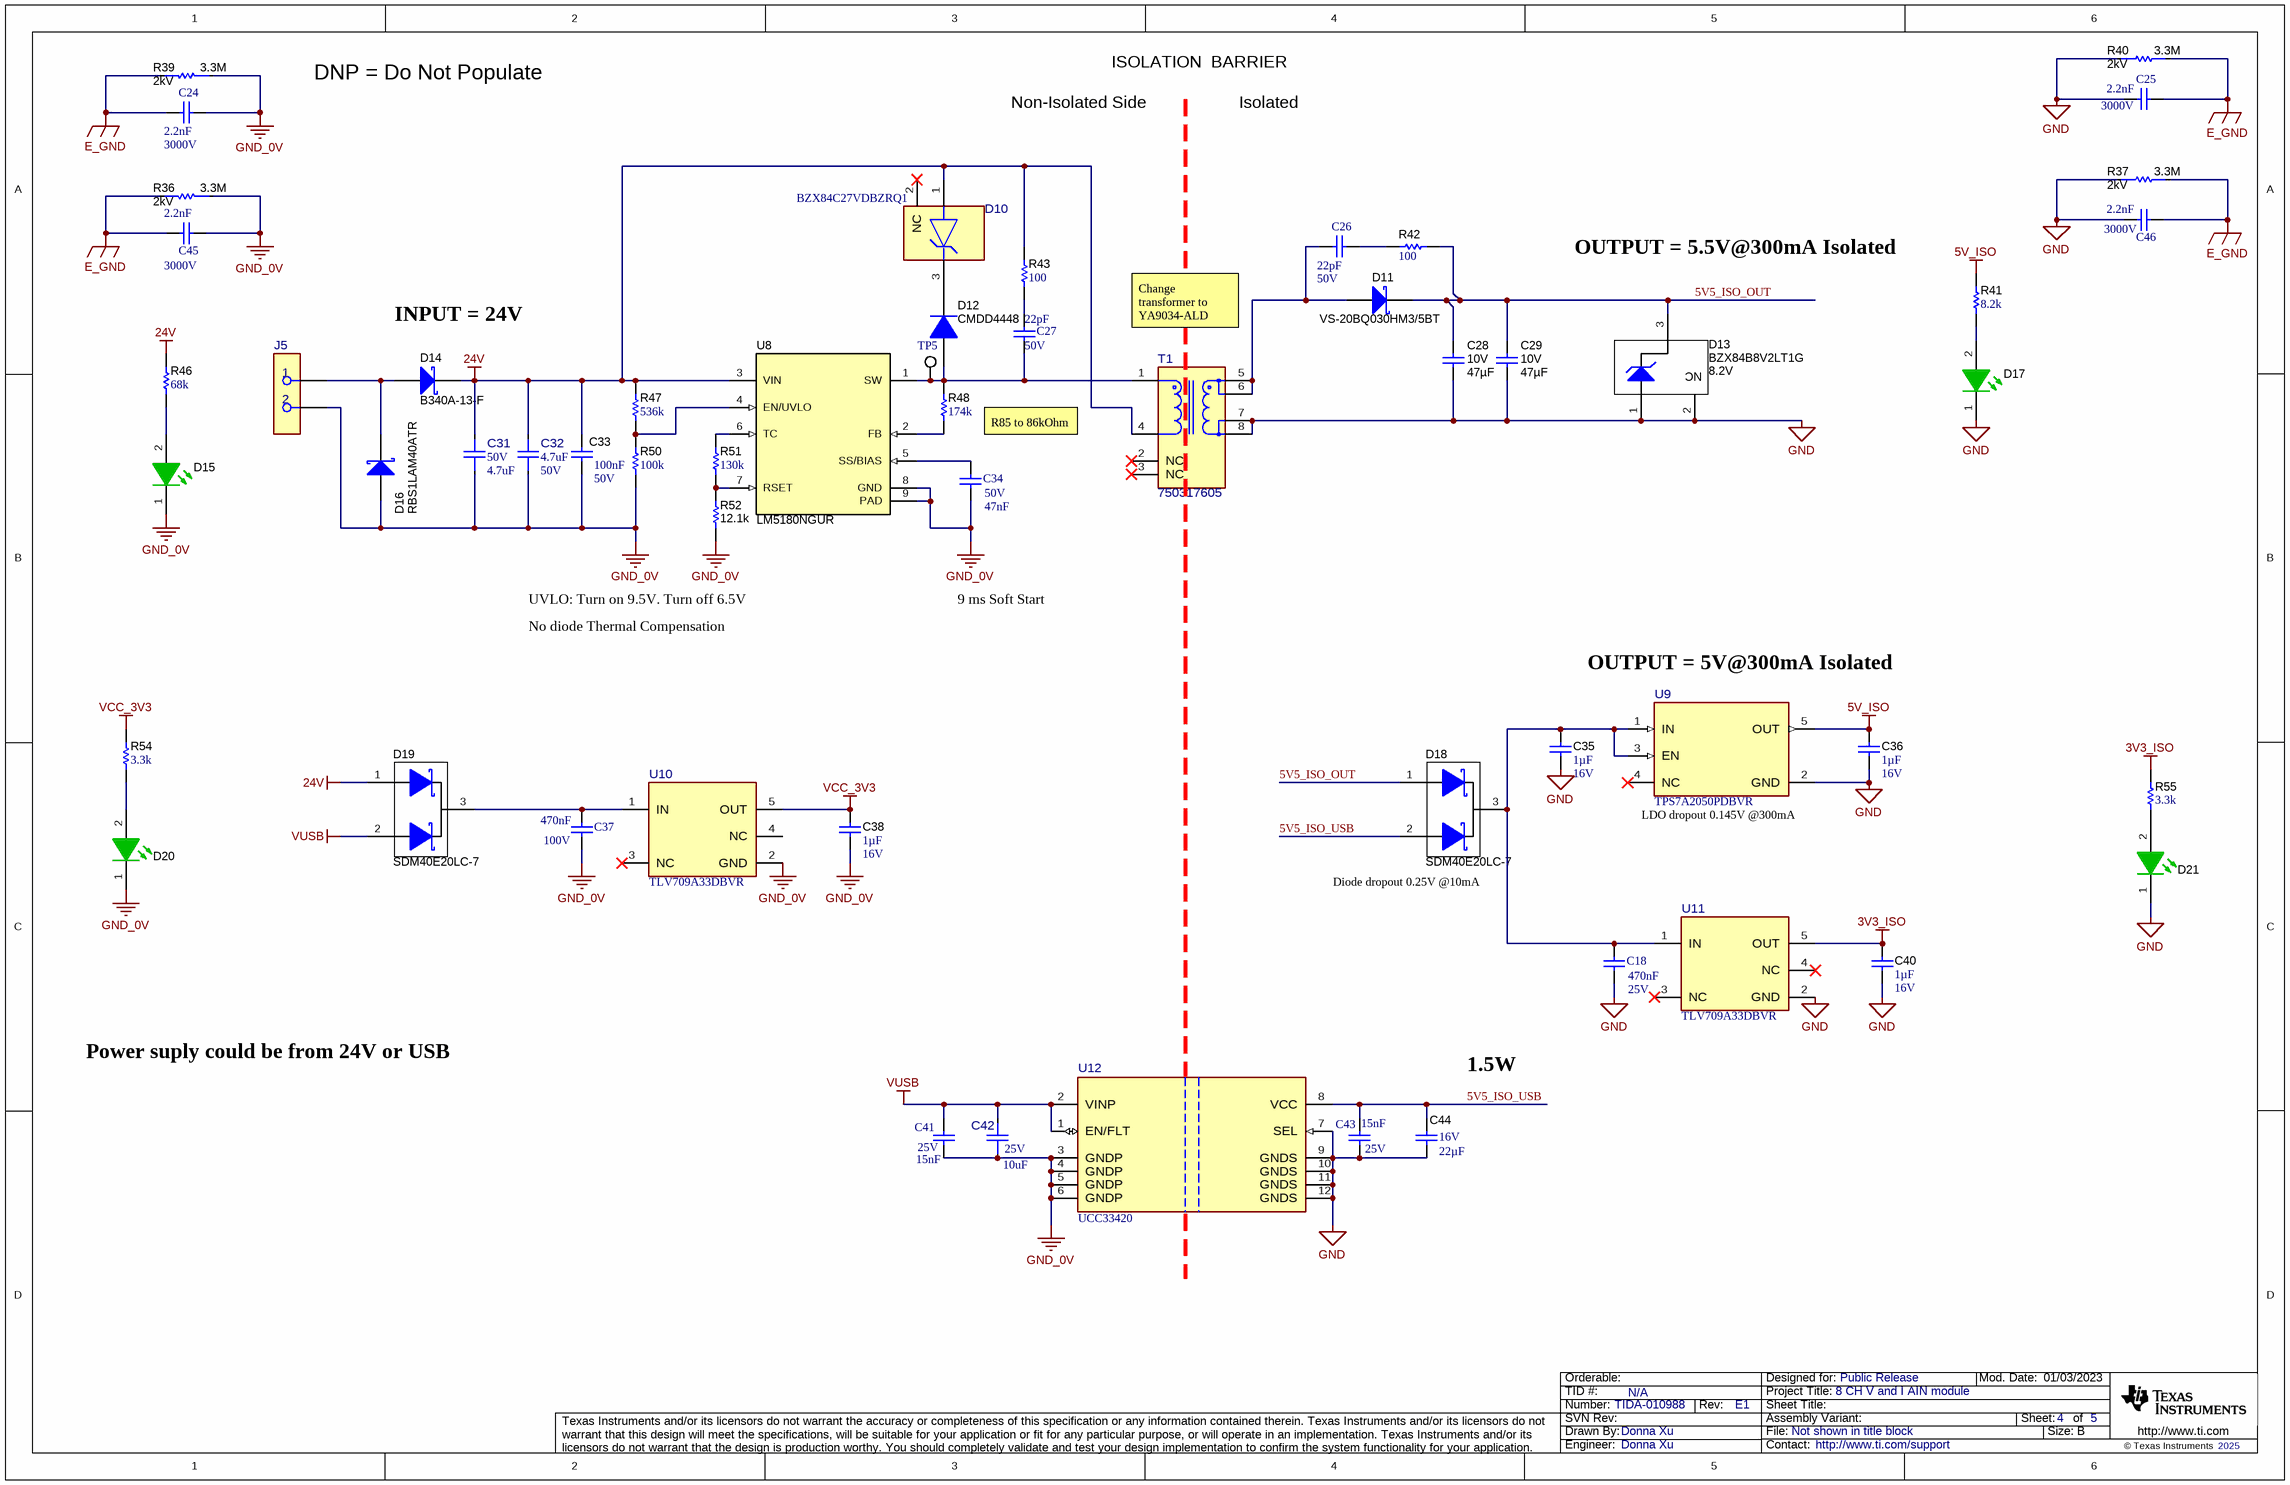
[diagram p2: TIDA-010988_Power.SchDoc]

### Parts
C18  Cap_F: 470nF  Rated Voltage (DC): 25V  [WCAP-CSGP_0603_L1.6W0.8H0.8_Reflow]  (hidden comment: 885012206075)
C24  Cap_F: 2.2nF  Rated Voltage (DC): 3000V  [WCAP-CSMH_1812_L4.5W3.2H2.5]  (hidden comment: 885342211010)
C25  Cap_F: 2.2nF  Rated Voltage (DC): 3000V  [WCAP-CSMH_1812_L4.5W3.2H2.5]  (hidden comment: 885342211010)
C26  Cap_F: 22pF  Rated Voltage (DC): 50V  [WCAP-CSGP_0805_L2W1.25H0.6_Reflow]  (hidden comment: 885012007053)
C27  Cap_F: 22pF  Rated Voltage (DC): 50V  [WCAP-CSGP_0805_L2W1.25H0.6_Reflow]  (hidden comment: 885012007053)
C28  VDC_V: 10V  ValueDisplayed: 47µF  [0805]  (hidden comment: GRM21BR61A476ME15L)
C29  VDC_V: 10V  ValueDisplayed: 47µF  [0805]  (hidden comment: GRM21BR61A476ME15L)
C31  VDC_V: 50V  ValueDisplayed: 4.7uF  [FP-885012208094_1206-MFG]  (hidden comment: 885012208094)
C32  ValueDisplayed: 4.7uF  VDC_V: 50V  [FP-885012209048_1210-MFG]  (hidden comment: 885012209048)
C33  Cap_F: 100nF  VDC_V: 50V  [0603]  (hidden comment: 885012206095)
C34  Cap_F: 47nF  Rated Voltage (DC): 50V  [WCAP-CSGP_0603_L1.6W0.8H0.8_Reflow]  (hidden comment: 885012206093)
C35  Cap_F: 1µF  VDC_V: 16V  [0603]  (hidden comment: 885012206052)
C36  Cap_F: 1µF  VDC_V: 16V  [0603]  (hidden comment: 885012206052)
C37  Cap_F: 470nF  Rated Voltage (DC): 100V  [WCAP-CSGP_0805_L2W1.25H1.25]  (hidden comment: 885012207130)
C38  Cap_F: 1µF  VDC_V: 16V  [0603]  (hidden comment: 885012206052)
C40  Cap_F: 1µF  VDC_V: 16V  [0603]  (hidden comment: 885012206052)
C41  Cap_F: 15nF  Rated Voltage (DC): 25V  [WCAP-CSGP_0603_L1.6W0.8H0.8_Reflow]  (hidden comment: 885012206066)
C42  ValueDisplayed: 10uF  VDC_V: 25V  [FP-885012106031_0603-MFG]  (hidden comment: 885012106031)
C43  Cap_F: 15nF  Rated Voltage (DC): 25V  [WCAP-CSGP_0603_L1.6W0.8H0.8_Reflow]  (hidden comment: 885012206066)
C44  VDC_V: 16V  ValueDisplayed: 22µF  [0603]  (hidden comment: CL10A226MO7JZNC)
C45  Cap_F: 2.2nF  Rated Voltage (DC): 3000V  [WCAP-CSMH_1812_L4.5W3.2H2.5]  (hidden comment: 885342211010)
C46  Cap_F: 2.2nF  Rated Voltage (DC): 3000V  [WCAP-CSMH_1812_L4.5W3.2H2.5]  (hidden comment: 885342211010)
D10  BZX84C27VDBZRQ1  [DBZ0003A-MFG]
D11  VS-20BQ030HM3/5BT  [SMB]
D12  CMDD4448  [SOD-323]
D13  BZX84B8V2LT1G  value 8.2V  [SOT-23]
D14  B340A-13-F  [SMA]
D15  150040GS73240  [WL-SMCC_0402_Green]  (value not drawn)
D16  RBS1LAM40ATR  [FP-RBS1LAM40ATR_SOD128-MFG]
D17  150040GS73240  [WL-SMCC_0402_Green]  (value not drawn)
D18  SDM40E20LC-7  [SOT-23]
D19  SDM40E20LC-7  [SOT-23]
D20  150040GS73240  [WL-SMCC_0402_Green]  (value not drawn)
D21  150040GS73240  [WL-SMCC_0402_Green]  (value not drawn)
J5  691103110002  [FP-691103110002_CONN_TERM_POS2-MFG]  (value not drawn)
R36  Res_ohm: 3.3M  VDC_V: 2kV  [FP-CHV2010-FX-3304ELF_2010-MFG]  (hidden comment: CHV2010-FX-3304ELF)
R37  Res_ohm: 3.3M  VDC_V: 2kV  [FP-CHV2010-FX-3304ELF_2010-MFG]  (hidden comment: CHV2010-FX-3304ELF)
R39  Res_ohm: 3.3M  VDC_V: 2kV  [FP-CHV2010-FX-3304ELF_2010-MFG]  (hidden comment: CHV2010-FX-3304ELF)
R40  Res_ohm: 3.3M  VDC_V: 2kV  [FP-CHV2010-FX-3304ELF_2010-MFG]  (hidden comment: CHV2010-FX-3304ELF)
R41  ValueDisplayed: 8.2k  [0402]  (hidden comment: CRCW04028K20JNED)
R42  ValueDisplayed: 100  [0805]  (hidden comment: RG2012P-101-B-T5)
R43  ValueDisplayed: 100  [0805]  (hidden comment: RG2012P-101-B-T5)
R46  ValueDisplayed: 68k  [0402]  (hidden comment: CRCW040268K0JNED)
R47  ValueDisplayed: 536k  [0603S]  (hidden comment: RC0603FR-07536KL)
R48  ValueDisplayed: 174k  [0603]  (hidden comment: RC0603FR-07174KL)
R50  ValueDisplayed: 100k  [0603S]  (hidden comment: RC0603FR-07100KL)
R51  ValueDisplayed: 130k  [0603]  (hidden comment: RC0603FR-07130KL)
R52  ValueDisplayed: 12.1k  [0603S]  (hidden comment: RC0603FR-0712K1L)
R54  ValueDisplayed: 3.3k  [0402]  (hidden comment: CRCW04023K30JNED)
R55  ValueDisplayed: 3.3k  [0402]  (hidden comment: CRCW04023K30JNED)
T1  750317605  [FP-750317605_SMT_XFRMR_9MM5_9MM78-MFG]
TP5  SW  [Testpoint_Keystone_Miniature]  (value not drawn)
U8  LM5180NGUR  [NGU0008C]
U9  TPS7A2050PDBVR  [DBV0005A-MFG]
U10  TLV709A33DBVR  [DBV0005A-MFG]
U11  TLV709A33DBVR  [DBV0005A-MFG]
U12  UCC33420  [RAQ0012B-MFG]

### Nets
3V3_ISO: C40.1 R55.1 U11.5(OUT)
5V_ISO: C36.1 R41.2 U9.5(OUT)
24V: C31.2 C32.2 C33.1 D10.1(A) D14.1(K) D19.1(A) R43.2 R46.2 R47.2 T1.4 U8.3(VIN)
E_GND: C24.1 C25.2 C45.1 C46.2 R36.2 R37.2 R39.2 R40.2
GND: C18.1 C25.1 C28.2 C29.2 C35.2 C36.2 C40.2 C43.1 C44.2 C46.1 D13.1(A) D13.2(NC) D17.1(K) D21.1(K) R37.1 R40.1 T1.7 T1.8 U9.2(GND) U11.2(GND) U12.7(SEL) U12.9(GNDS) U12.10(GNDS) U12.11(GNDS) U12.12(GNDS)
GND_0V: C24.2 C31.1 C32.1 C33.2 C34.1 C37.1 C38.2 C41.1 C42.1 C45.2 D15.1(K) D16.2(A) D20.1(K) J5.2 R36.1 R39.1 R50.1 R52.1 U8.8(GND) U8.9(PAD) U10.2(GND) U12.3(GNDP) U12.4(GNDP) U12.5(GNDP) U12.6(GNDP)
VCC_3V3: C38.1 R54.1 U10.5(OUT)
VUSB: C41.2 C42.2 D19.2(A) U12.1(EN/FLT) U12.2(VINP)
5V5_ISO_OUT: C28.1 C29.1 D11.1(K) D13.3(K) D18.1(A) R42.2
5V5_ISO_USB: C43.2 C44.1 D18.2(A) U12.8(VCC)
NetC18_2: C18.2 C35.1 D18.3(K) U9.1(IN) U9.3(EN) U11.1(IN)
NetC26_1: C26.1 D11.2(A) T1.5 T1.6
NetC26_2: C26.2 R42.1
NetC27_1: C27.1 D12.2(A) R48.2 T1.1 TP5.1 U8.1(SW)
NetC27_2: C27.2 R43.1
NetC34_2: C34.2 U8.5(SS/BIAS)
NetC37_2: C37.2 D19.3(K) U10.1(IN)
NetD10_3: D10.3(K) D12.1(K)
NetD14_2: D14.2(A) D16.1(K) J5.1
NetD15_2: D15.2(A) R46.1
NetD17_2: D17.2(A) R41.1
NetD20_2: D20.2(A) R54.2
NetD21_2: D21.2(A) R55.2
NetR47_1: R47.1 R50.2 U8.4(EN/UVLO)
NetR48_1: R48.1 U8.2(FB)
NetR51_1: R51.1 R52.2 U8.7(RSET)
NetR51_2: R51.2 U8.6(TC)

Not connected (* = marked no-connect by the designer): D10 2(NC)*; T1 2(NC)* 3(NC)*; U9 4(NC)*; U10 3(NC)* 4(NC); U11 3(NC)* 4(NC)*

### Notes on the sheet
- DNP = Do Not Populate
- ISOLATION  BARRIER
- Non-Isolated Side
- Isolated Side
- OUTPUT = 5.5V@300mA Isolated
- INPUT = 24V
- Change transformer to YA9034-ALD
- R85 to 86kOhm
- UVLO: Turn on 9.5V. Turn off 6.5V
- No diode Thermal Compensation
- 9 ms Soft Start
- OUTPUT = 5V@300mA Isolated
- (near U9) LDO dropout 0.145V @300mA
- (near D18) Diode dropout 0.25V @10mA
- Power suply could be from 24V or USB
- 1.5W

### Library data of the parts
C18 = CMP-0119379-1: WCAP-CSGP Multilayer Ceramic Chip Capacitor, General Purpose, size 0603, X7R, 470nF, 25VDC; Manufacturer: Wurth Elektronik; Capacitance Tolerance: +/-10%; Case/Size Code: 0603; Dissipation Factor: 10%; Insulation Resistance: 1.1GOhm; Technical Reference: X7R0603474K025DFCT10000
C24 C25 = CMP-0119848-1: WCAP-CSMH Multilayer Ceramic Chip Capacitor, Mid and High Voltage, size 1812, X7R Class II, 2.2nF, 3000VDC; Manufacturer: Wurth Elektronik; Capacitance Tolerance: 10%; Case/Size Code: 1812; Dissipation Factor: 2.5%; Insulation Resistance: 10GOhm; Technical Reference: X7R1812222KC00DFCT10000
C26 C27 = CMP-0118967-1: WCAP-CSGP Multilayer Ceramic Chip Capacitor, General Purpose, size 0805, NP0, 22pF, 50VDC; Manufacturer: Wurth Elektronik; Capacitance Tolerance: +/-5%; Case/Size Code: 0805; Insulation Resistance: 10GOhm; Q Factor: 840; Technical Reference: NP00805220J050DFCT10000
C28 C29 = CMP-0078699-1: CAP, CERM, 47 µF, 10 V,+/- 20%, X5R, 0805; Manufacturer: MuRata; TaMin_C: -55°C; Polarized: N; Green_Lifecycle: Active; SizeAreaWB_mm2: 6.75; Green_REACh: Passed; U/M: EA; Value: 47uF; TaMax_C: 85°C; SizeZ_mm: 1.45; SizeX_mm: 2; SizeY_mm: 1.25; SizeArea_mm2: 2.5; Cap_F: 47 µF; AEC Category: Q200
C31 = CMP-0088282-2: 4.7µF ±10% 50V Ceramic Capacitor X7R 1206 (3216 Metric); Manufacturer: Wurth Electronics; TempCo: 15%; Symbol Name: SYM-885012208094; SizeZ_mm: 1.9mm; AEC Qualified: No
C32 = CMP-0096739-1: 4.7 µF ±10% 50V Ceramic Capacitor X7R 1210 (3225 Metric); Manufacturer: Wurth; TempCo: 15%; Cap_F: 4.7µF; AEC Qualified: No; SizeZ_mm: 2.7mm; Value: 4.7µF
C33 = CMP-0006837-4: CAP, CERM, 0.1 uF, 50 V, +/- 10%, X7R, 0603; Manufacturer: Wurth Elektronik; TaMin_C: -55°C; Polarized: N; SizeAreaWB_mm2: 4.68; Value1: Unknown; U/M: EA; Value: 0.1uF; TaMax_C: 125°C; SizeZ_mm: 1; SizeX_mm: 1.6; SizeY_mm: 0.8; SizeArea_mm2: 1.28; AEC Category: Q200
C34 = CMP-0119400-1: WCAP-CSGP Multilayer Ceramic Chip Capacitor, General Purpose, size 0603, X7R, 47nF, 50VDC; Manufacturer: Wurth Elektronik; Capacitance Tolerance: +/-10%; Case/Size Code: 0603; Dissipation Factor: 3%; Insulation Resistance: 10GOhm; Technical Reference: X7R0603473K050DFCT10000
C35 C36 C38 C40 = CMP-0006831-4: CAP, CERM, 1 uF, 16 V, +/- 10%, X7R, 0603; Manufacturer: Wurth Elektronik; TaMin_C: -55°C; Polarized: N; SizeAreaWB_mm2: 4.68; Value1: Unknown; U/M: EA; Value: 1uF; TaMax_C: 125°C; SizeZ_mm: 1; SizeX_mm: 1.6; SizeY_mm: 0.8; SizeArea_mm2: 1.28; AEC Category: Q200
C37 = CMP-0119543-1: WCAP-CSGP Multilayer Ceramic Chip Capacitor, General Purpose, size 0805, X7R Class II, 470nF, 100VDC; Manufacturer: Wurth Elektronik; Capacitance Tolerance: +/-10%; Case/Size Code: 0805; Dissipation Factor: 10%; Insulation Resistance: 0.2GOhm; Technical Reference: X7R0805474K100DFCT10000
C41 C43 = CMP-0119369-1: WCAP-CSGP Multilayer Ceramic Chip Capacitor, General Purpose, size 0603, X7R, 15nF, 25VDC; Manufacturer: Wurth Elektronik; Capacitance Tolerance: +/-10%; Case/Size Code: 0603; Dissipation Factor: 3.5%; Insulation Resistance: 10GOhm; Technical Reference: X7R0603153K025DFCT10000
C42 = CMP-0096736-1: 10 µF ±20% 25V Ceramic Capacitor X5R 0603 (1608 Metric); Manufacturer: Wurth; Cap_F: 10µF; AEC Qualified: No; SizeZ_mm: 1mm; Value: 10µF; TempCo: 15%
C44 = CMP-0081159-1: CAP, CERM, 22 µF, 16 V,+/- 20%, X5R, 0603; Manufacturer: Samsung; SizeAreaWB_mm2: 4.68; SizeArea_mm2: 1.28; AEC Qualified: N; AEC Category: Q200; Value: 22uF; TaMax_C: 85°C; SizeZ_mm: 1; TaMin_C: -55°C; SizeY_mm: 0.8; U/M: EA; SizeX_mm: 1.6
C45 C46 = CMP-0115919-1: WCAP-CSMH Multilayer Ceramic Chip Capacitor, Mid and High Voltage, size 1812, X7R Class II, 2.2nF, 3000VDC; Manufacturer: Wurth Elektronik; Capacitance Tolerance: 10%; Case/Size Code: 1812; Dissipation Factor: 2.5%; Insulation Resistance: 10GOhm; Technical Reference: X7R1812222KC00DFCT10000
D10 = CMP-0126396-1: Zener Diode 27 V 250 mW ±5% Surface Mount SOT-23-3; Manufacturer: Texas Instruments; AEC Qualified: Yes; SizeZ_mm: 1.12mm; Vf_V: 28.35V; Vr_V: 18.9V; AEC Grade: Grade 0; Max Reverse Leakage Current: 0.03uA; Power_W: 250mW; Standoff Height: 0.01mm; TaMax_C: +150°C; TaMin_C: -55°C; Vz_V: 27V; Zener Impedance: 80Ω
D11 = CMP-0028909-2: Diode, Schottky, 30 V, 2 A, AEC-Q101, SMB; Manufacturer: Vishay-Semiconductor; Io_A: 2A; Green_Lifecycle: Not Set; SizeAreaWB_mm2: 44.156; Vr_V: 30V; Green_REACh: Incomplete; TJmax_C: 150°C; Value: 30V; SizeZ_mm: 2.6; SizeX_mm: 5.6; SizeY_mm: 3.81; Vf_V: 470mV; Value2: 0.47V; SizeArea_mm2: 21.336; AEC Qualified: Y; AEC Category: Q101
D12 = CMP-0029019-2: Diode, Ultrafast, 75 V, 0.25 A, SOD-323; Manufacturer: Central Semiconductor; Io_A: 250mA; Green_Lifecycle: Not Set; SizeAreaWB_mm2: 8.695; Vr_V: 75V; Green_REACh: Incomplete; Value1: 0.25A; TJmax_C: 175°C; Value: 75V; SizeZ_mm: 1; SizeX_mm: 2.7; SizeY_mm: 1.35; Vf_V: 1.2V; SizeArea_mm2: 3.645; AEC Category: Q101
D13 = CMP-0005972-3: Diode, Zener, 8.2 V, 225 mW, SOT-23; Manufacturer: ON Semiconductor; Power_W: 225mW; SizeAreaWB_mm2: 14; Value1: 0.225W; RJA_CperW: 556; SizeZ_mm: 1.1; SizeX_mm: 2.5; SizeY_mm: 3; SizeArea_mm2: 7.5; AEC Category: Q101
D14 = CMP-0028353-2: Diode, Schottky, 40 V, 3 A, SMA; Manufacturer: Diodes Inc.; SizeAreaWB_mm2: 37.3428; Vf_V: 500mV; Value: 40V; Value1: 3A; Green_Lifecycle: Active; SizeX_mm: 5.59; Value2: 0.5V; TJmax_C: 125°C; SizeZ_mm: 2.87; SizeY_mm: 2.92; RJC_CperW: 25; Green_REACh: Passed; SizeArea_mm2: 16.3228; AEC Category: Q101
D15 D17 D20 D21 = CMP-0081765-2: as D3 on sheet TIDA-010988_ADC+MCU
D16 = CMP-0088101-2: DIODE SCHOTTKY 20V 1A PMDTM; Manufacturer: Rohm; SizeZ_mm: 1.05mm; TJmax_C: 125°C; Symbol Name: SYM-RBS1LAM40ATR; AEC Category: Q101; AEC Qualified: No
D18 D19 = CMP-0028570-2: Diode, Schottky, 20 V, 0.4 A, SOT-23; Manufacturer: Diodes Inc.; Green_REACh: Incomplete; SizeX_mm: 2.5; Value: 20V; Green_Lifecycle: Not Set; Vf_V: 350mV; AEC Category: Q101; SizeZ_mm: 1.1; SizeAreaWB_mm2: 14; Io_A: 400mA; Value2: 0.35V; SizeArea_mm2: 7.5; SizeY_mm: 3; Value1: 0.4A
J5 = CMP-0095471-2: 2 Position Wire to Board Terminal Block Horizontal with Board 0.138" (3.50mm) Through Hole; Manufacturer: Wurth; SizeZ_mm: 8.5mm; Conn Gender: Female; Min Wire Gauge: 26; ContactFinish: Tin,Nickel; Row_Count: 1; Current_A: 10A; Voltage_V: 125V; Max Wire Gauge: 16; DUT-Pitch_mm: 3.5mm; Is Female: yes; AEC Qualified: No
R36 R37 R39 R40 = CMP-0089022-1: RES SMD 3.3M OHM 1% 1/2W 2010; Manufacturer: Bourns; SizeZ_mm: 0.7mm; AEC Qualified: Yes; AEC Grade: Grade 0; Power_W: 500mW; TempCo: 100ppm/°C
R41 = CMP-0026982-5: RES, 8.2 k, 5%, 0.063 W, AEC-Q200 Grade 0, 0402; Manufacturer: Vishay-Dale; Power_W: 63mW; TempCo: 200 ppm/C; Value_Code: 8k20; Value: 8.2k; EIA_Code: E24; SizeX_mm: 1; SizeY_mm: 0.5; SizeZ_mm: 0.6; Value2: 0.063W; AEC Qualified: Y; VDC_V: 50V; AEC Category: Q200; AEC Grade: 0
R42 R43 = CMP-0018851-2: RES, 100, 0.1%, 0.125 W, 0805; Manufacturer: Susumu Co Ltd; Power_W: 125mW; TempCo: 25 ppm/C; Value_Code: 100R; U/M: EA; Value: 100; EIA_Code: E192; SizeX_mm: 2; SizeY_mm: 1.25; SizeZ_mm: 1.45; Value2: 0.125W; SizeArea_mm2: 2.5; VDC_V: 100V; AEC Category: Q200
R46 = CMP-0026963-3: RES, 68 k, 5%, 0.063 W, AEC-Q200 Grade 0, 0402; Manufacturer: Vishay-Dale; Power_W: 63mW; TempCo: 200 ppm/C; Value_Code: 68k0; Value: 68k; EIA_Code: E24; SizeX_mm: 1; SizeY_mm: 0.5; SizeZ_mm: 0.6; Value2: 0.063W; AEC Qualified: Y; VDC_V: 50V; AEC Category: Q200; AEC Grade: 0
R47 = CMP-0023174-4: RES, 536 k, 1%, 0.1 W, 0603; Manufacturer: Yageo; Power_W: 100mW; TempCo: 100 ppm/C; Value: 536k; EIA_Code: E96; SizeX_mm: 1.6; SizeY_mm: 0.8; SizeZ_mm: 1; Value2: 0.1W; SizeArea_mm2: 1.28; AEC Qualified: N; VDC_V: 75V; AEC Category: Q200; SizeAreaWB_mm2: 4.68
R48 = CMP-0022836-4: RES, 174 k, 1%, 0.1 W, 0603; Manufacturer: Yageo; Power_W: 100mW; TempCo: 100 ppm/C; Value: 174k; EIA_Code: E96; SizeX_mm: 1.6; SizeY_mm: 0.8; SizeZ_mm: 1; Value2: 0.1W; SizeArea_mm2: 1.28; AEC Qualified: N; VDC_V: 75V; AEC Category: Q200; SizeAreaWB_mm2: 4.68
R50 = CMP-0022735-5: RES, 100 k, 1%, 0.1 W, 0603; Manufacturer: Yageo; Power_W: 100mW; TempCo: 100 ppm/C; Value: 100k; EIA_Code: E96; SizeX_mm: 1.6; SizeY_mm: 0.8; SizeZ_mm: 1; Value2: 0.1W; SizeArea_mm2: 1.28; AEC Qualified: N; VDC_V: 75V; AEC Category: Q200; SizeAreaWB_mm2: 4.68
R51 = CMP-0022784-4: RES, 130 k, 1%, 0.1 W, 0603; Manufacturer: Yageo; Power_W: 100mW; TempCo: 100 ppm/C; Value: 130k; EIA_Code: E96; SizeX_mm: 1.6; SizeY_mm: 0.8; SizeZ_mm: 1; Value2: 0.1W; SizeArea_mm2: 1.28; AEC Qualified: N; VDC_V: 75V; AEC Category: Q200; SizeAreaWB_mm2: 4.68
R52 = CMP-0022776-5: RES, 12.1 k, 1%, 0.1 W, 0603; Manufacturer: Yageo; Power_W: 100mW; TempCo: 100 ppm/C; Value_Code: 12k1; Value: 12.1k; EIA_Code: E96; SizeX_mm: 1.6; SizeY_mm: 0.8; SizeZ_mm: 1; Value2: 0.1W; SizeArea_mm2: 1.28; AEC Qualified: N; VDC_V: 75V; AEC Category: Q200; SizeAreaWB_mm2: 4.68
R54 R55 = CMP-0026918-5: as R34 on sheet TIDA-010988_ADC+MCU
T1 = CMP-0096072-1: Transformer, 0.13Ohm PRI, 0.019Ohm SEC, 3:1, 9.5x9.78x10.54mm SMT; Manufacturer: Wurth Electronics; Frequency_Fixed: 350kHz; AEC Qualified: No; DCR_ohm: 0.13; Ind_H: 30µH; Rsec1_ohm: 19m
TP5 = CMP-0055152-2: Test Point, Miniature, SMT; Manufacturer: Keystone Electronics; CT: TRUE; Green_Lifecycle: Active; Green_REACh: Passed; CNHeader: FALSE
U8 = CMP-0084791-1: 70-VIN PSR Flyback DC/DC Converter With 100-V, 1.5-A Integrated Power MOSFET, NGU0008C (WSON-8); Manufacturer: Texas Instruments; Alternate PartNumber: LM5180NGUT; AEC Qualified: N; SizeY_mm: 4; SizeArea_mm2: 16; CompType: IC; SizeAreaWB_mm2: 25; SizeZ_mm: 0.8; AEC Category: Q200
U9 = CMP-0091339-1: 300-mA, ultra-low-noise, low-IQ, low-dropout (LDO) linear regulator with high PSRR 5-SOT-23 -40 to 125; Manufacturer: Texas Instruments; Nominal Supply Current: 6.5uA; Number Of Outputs: 1; Max Supply Voltage: 6V; TJmax_C: +125°C; Accuracy Percentage: 1.5%; SizeZ_mm: 1.45mm; Dropout Voltage: 140mV; Output Voltage: 5V; Min Supply Voltage: 1.6V; Output Type: Fixed; AEC Qualified: No; Standoff Height: 0mm
U10 U11 = CMP-0034271-1: 150-mA 30-V low-dropout (LDO) linear regulator with 3.2-μA supply current 5-SOT-23 -40 to 125; Manufacturer: Texas Instruments; SizeZ_mm: 1.45mm; AEC Qualified: No; Accuracy Percentage: 4%; Dropout Voltage: 1000mV; Max Supply Voltage: 30V; Min Supply Voltage: 4.3V; Nominal Supply Current: 3.2uA; Number Of Outputs: 1; Output Type: Fixed; Output Voltage: 3.3V; Standoff Height: 0mm; TJmax_C: +125°C
U12 = CMP-0098322-4: 1.5W, High-Density, >3 kVRMS Isolated DC-DC Converter; Manufacturer: Texas Instruments; SizeZ_mm: 1.05mm; AEC Qualified: No; AEC Grade: NA; Max Supply Voltage: 5.5V; Min Supply Voltage: 4.5V; Number Of Outputs: 1; Output Type: Fixed; Output Voltage: 5V; AEC Category: Q200; CompType: IC

## Sheet TIDA-010988_Hardware.SchDoc: Hardware
size 431 x 279 mm; Date: Not shown in title block; ApprovedBy: Not shown in title block; CheckedBy: Not shown in title block; Author: Not shown in title block; CompanyName: Not shown in title block; Engineer: Not shown in title block; Organization: Not shown in title block; Address1: Not shown in title block; Address2: Not shown in title block; Address3: Not shown in title block; Address4: Not shown in title block; DocumentNumber: 3; Revision: Use project parameter SCH_Rev; SheetNumber: 5; SheetTotal: 5; PageSetup: Record=PageOptions¦CenterHorizontal=True¦CenterVertical=True¦PrintScale=1.00¦XCorrection=1.00¦YCorrection=1.00¦PrintKind=0¦BorderSize=5000000¦LeftOffset=0¦BottomOffset=0¦Orientation=2¦PaperLength=1000¦PaperWidth=1000¦Scale=100¦PaperSource=15¦PrintQuality=600¦MediaType=1¦DitherType=10¦PaperKind=Letter¦PrintScaleMode=1
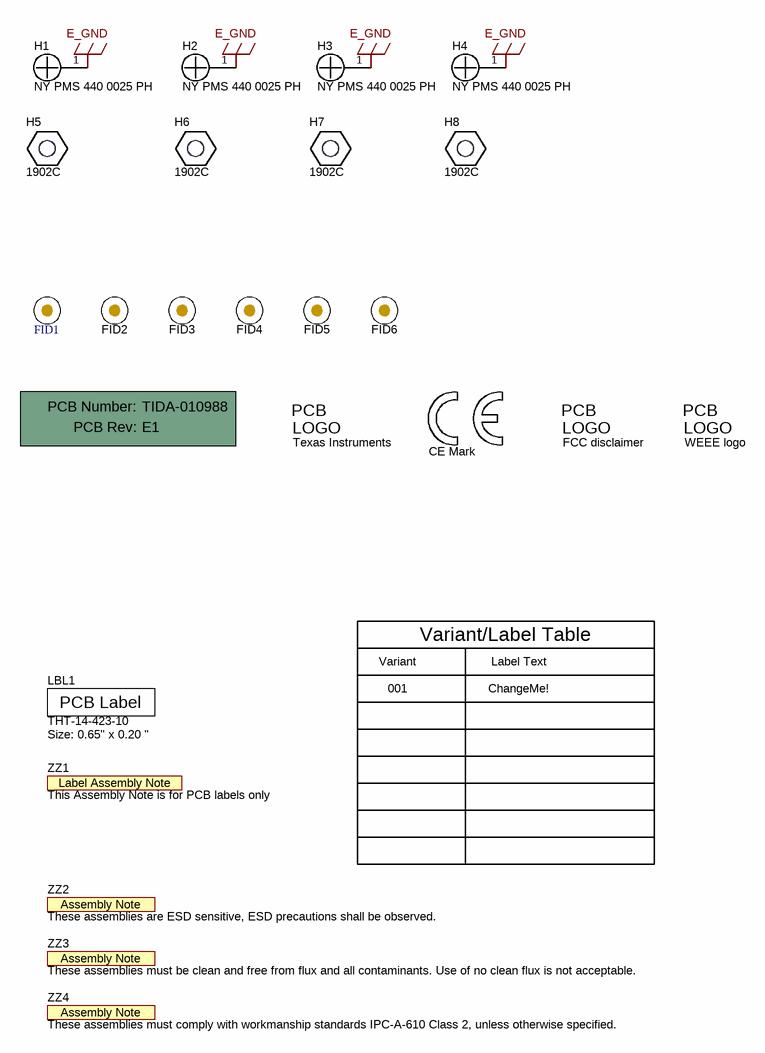
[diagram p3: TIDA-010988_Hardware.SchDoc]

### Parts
!PCB1  Printed Circuit Board  (value not drawn)  (mechanical)
FID1  Fiducial  [Fiducial10-20]  (value not drawn)
FID2  Fiducial  [Fiducial10-20]  (value not drawn)
FID3  Fiducial  [Fiducial10-20]  (value not drawn)
FID4  Fiducial  [Fiducial10-20]  (value not drawn)
FID5  Fiducial  [Fiducial10-20]  (value not drawn)
FID6  Fiducial  [Fiducial10-20]  (value not drawn)
H1  NY PMS 440 0025 PH  [NY PMS 440 0025 PH]
H2  NY PMS 440 0025 PH  [NY PMS 440 0025 PH]
H3  NY PMS 440 0025 PH  [NY PMS 440 0025 PH]
H4  NY PMS 440 0025 PH  [NY PMS 440 0025 PH]
H5  1902C  [Keystone_1902C]
H6  1902C  [Keystone_1902C]
H7  1902C  [Keystone_1902C]
H8  1902C  [Keystone_1902C]
LBL1  THT-14-423-10  Note: Size: 0.65" x 0.20 "  [Label_650x200]
Logo1  CE Mark  [CE_Mark_5mm]  (no BOM)
Logo2  Texas Instruments  [TI_Stacked_Overlay_Small]  (no BOM)
Logo3  FCC disclaimer  [FCC_disclaimer]  (no BOM)
Logo4  WEEE logo  [WEEE_Minimum]  (no BOM)
ZZ1  This Assembly Note is for PCB labels only  [AssemblyNoteLabel]  (no BOM)
ZZ2  These assemblies are ESD sensitive, ESD precautions shall be observed.  [AssemblyNote]  (no BOM)
ZZ3  These assemblies must be clean and free from flux and all contaminants. Use of no clean flux is not acceptable.  [AssemblyNote]  (no BOM)
ZZ4  These assemblies must comply with workmanship standards IPC-A-610 Class 2, unless otherwise specified.  [AssemblyNote]  (no BOM)

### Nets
E_GND: H1.1 H2.1 H3.1 H4.1

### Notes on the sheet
- Variant
- Variant/Label Table
- Label Text
- 001
- ChangeMe!

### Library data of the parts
!PCB1 = CMP-0003618-2: Manufacturer: Any; PartNumber: TIDA-010988
FID1-FID6 = CMP-0077181-1: Fiducial mark.  There is nothing to buy or mount.
H1-H4 = CMP-0003617-1: Machine Screw, Round, #4-40 x 1/4, Nylon, Philips panhead; Manufacturer: B&F Fastener Supply; CompType: Hardware
H5-H8 = CMP-0003610-1: Standoff, Hex, 0.5"L #4-40 Nylon; Manufacturer: Keystone; CompType: Hardware
LBL1 = CMP-0003625-1: Thermal Transfer Printable Labels, 0.650" W x 0.200" H - 10,000 per roll; Manufacturer: Brady; CompType: Label
Logo1 = CMP-0074844-2: Manufacturer: Texas Instruments; SymbolCreator: a0412235; AEC Category: Q200; CompType: IC
Logo2 = CMP-0074838-1: Texas Instrument Corporate Signature; SymbolCreator: a0412235; Lib Reference: TI_Logo; Library Reference: Logo
Logo3 = CMP-0074847-1: FCC_disclaimer; Library Reference: Logo
Logo4 = CMP-0074769-4: Manufacturer: Texas Instruments; CompType: IC; AEC Category: Q200
ZZ1 = CMP-0003616-3
ZZ2 = CMP-0077236-1
ZZ3 = CMP-0077237-1
ZZ4 = CMP-0077238-1

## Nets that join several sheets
3V3_ISO: TIDA-010988_ADC+MCU (L4.2), TIDA-010988_Power (C40.1 R55.1 U11.5)
5V_ISO: TIDA-010988_ADC+MCU (L5.2), TIDA-010988_Power (C36.1 R41.2 U9.5)
E_GND: TIDA-010988_Input (C1.2 C2.1 R1.1 R2.2), TIDA-010988_ADC+MCU (J2.Z1 J2.Z2 J2.Z3 J2.Z4), TIDA-010988_Power (8 pins), TIDA-010988_Hardware (H1.1 H2.1 H3.1 H4.1)
GND: TIDA-010988_Input (9 pins), TIDA-010988_ADC+MCU (28 pins), TIDA-010988_Power (25 pins)
GND_0V: TIDA-010988_ADC+MCU (27 pins), TIDA-010988_Power (25 pins)
VCC_3V3: TIDA-010988_ADC+MCU (10 pins), TIDA-010988_Power (C38.1 R54.1 U10.5)
VUSB: TIDA-010988_ADC+MCU (D6.2 J2.1 R7.2 R8.2), TIDA-010988_Power (5 pins)

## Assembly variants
001: not fitted C30 C45 C46 FID1 FID2 FID3 R0_1 R0_2 R0_3 R0_4 R0_5 R0_6 R0_7 R0_8 R36 R37 R51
